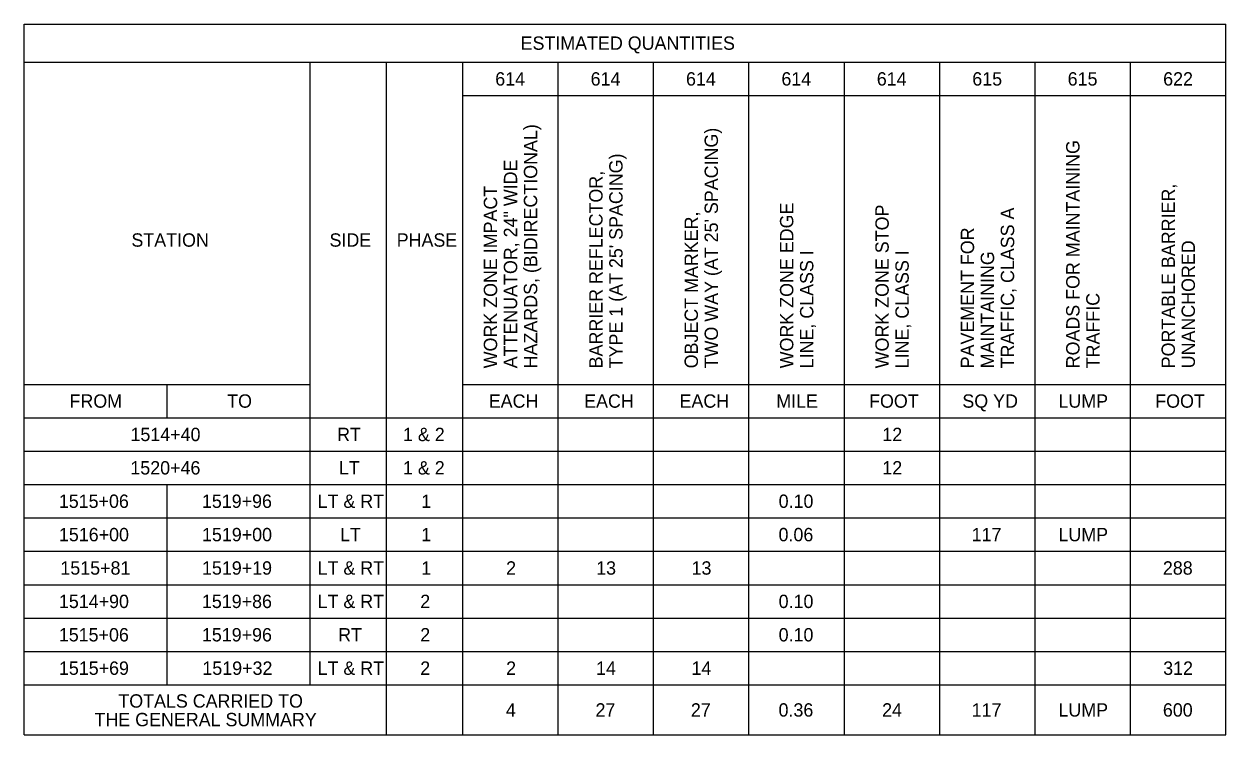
# Model space of a CAD drawing. Extents: x -1.9 to 59.7, y -1.6 to 50.3.
# Drawn here: x 47.13 to 59.73, y -1.6 to 5.86 of the extents above; entities that cross this region are included whole.
import ezdxf

# ---------------------------------------------------------------- set-up
doc = ezdxf.new("R2010")
doc.units = 0
doc.layers.add('SH_Text', color=7, linetype='Continuous')

msp = doc.modelspace()

# ---------------------------------------------------------------- linework, layer by layer
at = {"layer": 'SH_Text'}
for p, q in [((47.13, -1.595), (47.13, 5.857)), ((47.13, 5.857), (59.73, 5.857)), ((59.73, -1.595), (59.73, 5.857)), ((47.13, 5.457), (59.73, 5.457)), ((50.13, -1.07), (50.13, 5.457)), ((50.93, -1.595), (50.93, 5.457)), ((51.73, -1.595), (51.73, 5.457)), ((52.73, -1.595), (52.73, 5.457)), ((53.73, -1.595), (53.73, 5.457)), ((54.73, -1.595), (54.73, 5.457)), ((55.73, -1.595), (55.73, 5.457)), ((56.73, -1.595), (56.73, 5.457)), ((57.73, -1.595), (57.73, 5.457)), ((58.73, -1.595), (58.73, 5.457)), ((51.73, 5.107), (59.73, 5.107)), ((47.13, 2.08), (50.13, 2.08)), ((48.63, 1.73), (48.63, 2.08)), ((51.73, 2.08), (59.73, 2.08)), ((47.13, 1.73), (59.73, 1.73)), ((47.13, 1.38), (59.73, 1.38)), ((47.13, 1.03), (59.73, 1.03)), ((48.63, -1.07), (48.63, 1.03)), ((47.13, 0.68), (59.73, 0.68)), ((47.13, 0.33), (59.73, 0.33)), ((47.13, -0.02), (59.73, -0.02)), ((47.13, -0.37), (59.73, -0.37)), ((47.13, -0.72), (59.73, -0.72)), ((47.13, -1.07), (59.73, -1.07)), ((47.13, -1.595), (59.73, -1.595))]:
    msp.add_line(p, q, dxfattribs=at)

# ---------------------------------------------------------------- texts
for s, p in [('ESTIMATED QUANTITIES', (52.336, 5.587)), ('614', (52.07, 5.212)), ('614', (53.07, 5.212)), ('614', (54.07, 5.212)), ('614', (55.07, 5.212)), ('614', (56.07, 5.212)), ('615', (57.071, 5.212)), ('615', (58.071, 5.212)), ('622', (59.072, 5.212)), ('STATION', (48.256, 3.523)), ('SIDE', (50.333, 3.523)), ('PHASE', (51.037, 3.523)), ('FROM', (47.607, 1.835)), ('TO', (49.26, 1.835)), ('EACH', (52.002, 1.835)), ('EACH', (53.002, 1.835)), ('EACH', (54.002, 1.835)), ('MILE', (55.016, 1.835)), ('FOOT', (55.989, 1.835)), ('SQ YD', (56.967, 1.835)), ('LUMP', (57.974, 1.835)), ('FOOT', (58.989, 1.835)), ('1514+40', (48.246, 1.485)), ('RT', (50.412, 1.485)), ('1 & 2', (51.103, 1.485)), ('12', (56.128, 1.485)), ('1520+46', (48.245, 1.135)), ('LT', (50.431, 1.135)), ('1 & 2', (51.103, 1.135)), ('12', (56.128, 1.135)), ('1515+06', (47.495, 0.785)), ('1519+96', (48.995, 0.785)), ('LT & RT', (50.208, 0.785)), ('1', (51.295, 0.785)), ('0.10', (55.041, 0.785)), ('1516+00', (47.496, 0.435)), ('1519+00', (48.996, 0.435)), ('LT', (50.443, 0.435)), ('1', (51.295, 0.435)), ('0.06', (55.04, 0.435)), ('117', (57.065, 0.435)), ('LUMP', (57.974, 0.435)), ('1515+81', (47.511, 0.085)), ('1519+19', (48.996, 0.085)), ('LT & RT', (50.208, 0.085)), ('1', (51.295, 0.085)), ('2', (52.184, 0.085)), ('13', (53.128, 0.085)), ('13', (54.128, 0.085)), ('288', (59.069, 0.085)), ('1514+90', (47.496, -0.265)), ('1519+86', (48.995, -0.265)), ('LT & RT', (50.208, -0.265)), ('2', (51.284, -0.265)), ('0.10', (55.041, -0.265)), ('1515+06', (47.495, -0.615)), ('1519+96', (48.995, -0.615)), ('RT', (50.423, -0.615)), ('2', (51.284, -0.615)), ('0.10', (55.041, -0.615)), ('1515+69', (47.496, -0.965)), ('1519+32', (49, -0.965)), ('LT & RT', (50.208, -0.965)), ('2', (51.284, -0.965)), ('2', (52.184, -0.965)), ('14', (53.127, -0.965)), ('14', (54.127, -0.965)), ('312', (59.072, -0.965)), ('TOTALS CARRIED TO', (48.119, -1.309)), ('THE GENERAL SUMMARY', (47.869, -1.504)), ('4', (52.182, -1.403)), ('27', (53.121, -1.403)), ('27', (54.121, -1.403)), ('0.36', (55.04, -1.403)), ('24', (56.126, -1.403)), ('117', (57.065, -1.403)), ('LUMP', (57.974, -1.403)), ('600', (59.069, -1.403))]:
    msp.add_text(s, height=0.14, dxfattribs=at).set_placement(p)
for s, p in [('HAZARDS, (BIDIRECTIONAL)', (52.51, 2.248)), ("TWO WAY (AT 25' SPACING)", (54.405, 2.248)), ('ROADS FOR MAINTAINING', (58.195, 2.248)), ('ATTENUATOR, 24" WIDE', (52.3, 2.248)), ("TYPE 1 (AT 25' SPACING)", (53.405, 2.248)), ('BARRIER REFLECTOR,', (53.195, 2.248)), ('PORTABLE BARRIER,', (59.195, 2.248)), ('WORK ZONE IMPACT', (52.09, 2.248)), ('WORK ZONE EDGE', (55.195, 2.248)), ('WORK ZONE STOP', (56.195, 2.248)), ('TRAFFIC, CLASS A', (57.51, 2.248)), ('OBJECT MARKER,', (54.195, 2.248)), ('PAVEMENT FOR', (57.09, 2.248)), ('UNANCHORED', (59.405, 2.248)), ('LINE, CLASS I', (55.405, 2.248)), ('LINE, CLASS I', (56.405, 2.248)), ('MAINTAINING', (57.3, 2.248)), ('TRAFFIC', (58.405, 2.248))]:
    msp.add_text(s, height=0.14, rotation=90, dxfattribs=at).set_placement(p)

doc.saveas('drawing.dxf')
